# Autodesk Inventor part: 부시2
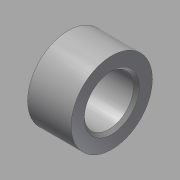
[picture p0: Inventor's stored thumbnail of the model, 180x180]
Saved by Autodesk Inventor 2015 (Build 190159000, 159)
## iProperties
Created: 2015-09
Part Number: 부시2
Material: 강철, 연강
Document SubType Name: Modeling
Designer: mduedu
Density: 7.86 g/cm^3
Description: 외주 가공
Mass: 45.4 g
Surface Area: 28.3815 cm^2
Volume: 5.77608 cm^3
Appearance: 강철
Author: mduedu
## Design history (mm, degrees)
sketch "스케치1"
  geometry: C1 r 14 at (0, 0); C2 r 8.5 at (0, 0); 1 further point
  constraints: 2 centre point, 2 coincident
  dimensions: "d0" = 28 diameter of C1; "d2" = 17 diameter of C2
extrude "돌출1" new body sketch "스케치1" distance "d3" = 15; taper "d4" = 0 deg
chamfer "모따기1" distance "d5" = 1; stored, may be unused: second distance "d6" = 2, angle "d7" = 45 deg
node "솔리드1"
